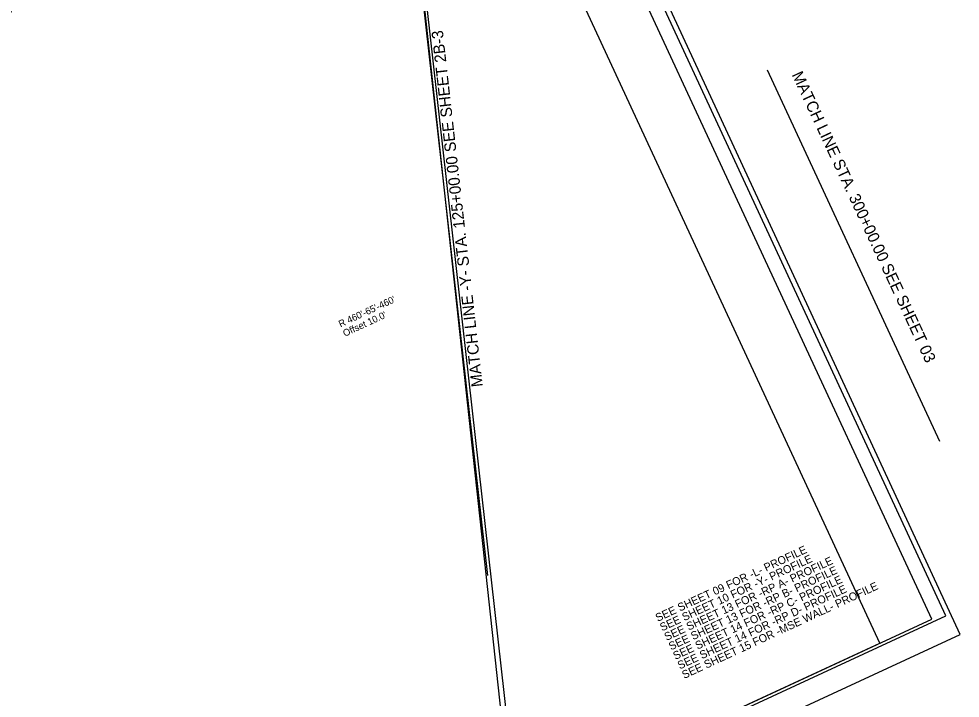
# Model space of a CAD drawing. Extents: x 1722892 to 1724880, y 971019 to 972720.
# Drawn here: x 1724057 to 1724880, y 971671 to 972266 of the extents above; entities that cross this region are included whole.
import ezdxf

# ---------------------------------------------------------------- set-up
doc = ezdxf.new("R2010")
doc.units = 0
for name, color, linetype in [('Matchline', 7, 'Continuous'), ('Matchline Text', 7, 'Continuous'), ('Prop Dimension', 7, 'Continuous'), ('Sheet Clip Boundary CELL', 7, 'Continuous'), ('Sheet Layout Plan Border', 7, 'Continuous'), ('Sheet Plan CELL', 7, 'Continuous'), ('Sheet Plot Border Inside CELL', 7, 'Continuous'), ('Sheet Plot Border Outside CELL', 7, 'Continuous')]:
    doc.layers.add(name, color=color, linetype=linetype)

msp = doc.modelspace()

# ---------------------------------------------------------------- linework, layer by layer
at = {"layer": 'Matchline'}
for p, q in [((1724467.08, 971778.29), (1724395.09, 972418.33)), ((1724711.39, 972221), (1724861.99, 971896.04))]:
    msp.add_line(p, q, dxfattribs=at)
at = {"layer": 'Sheet Clip Boundary CELL'}
msp.add_lwpolyline([(1723539.64, 971130.3), (1724809.87, 971718.99), (1724457.28, 972479.77), (1724285.57, 972400.19), (1724196.64, 972592.07), (1723098.13, 972082.96)], close=True, dxfattribs=at)
at = {"layer": 'Sheet Layout Plan Border'}
for points in [[(1724374.31, 972628.66), (1724393.21, 972460.35), (1724068.11, 972404.72), (1724049.69, 972271.07), (1723832.27, 972270.2), (1723815.72, 972244.69), (1723599.72, 972315.43), (1723098.13, 972082.96), (1723600.74, 971158.62), (1723483.33, 971374.55), (1723802.12, 971464.67), (1724031.92, 971474.7), (1724072.16, 971562.21), (1724326.28, 971494.87), (1724493, 971572.14)], [(1724391.63, 972460.07), (1724068.11, 972404.72), (1724049.69, 972271.07), (1723832.27, 972270.2), (1723815.72, 972244.69), (1723599.72, 972315.43), (1723098.13, 972082.96), (1723600.74, 971158.62), (1723483.33, 971374.55), (1723802.12, 971464.67), (1724031.92, 971474.7), (1724072.16, 971562.21), (1724326.28, 971494.87), (1724488.18, 971569.9)]]:
    msp.add_lwpolyline(points, close=True, dxfattribs=at)
at = {"layer": 'Sheet Plan CELL'}
msp.add_lwpolyline([(1724413.74, 972692.69), (1723052.76, 972061.94), (1723494.28, 971109.28), (1724855.24, 971740.02)], close=True, dxfattribs=at)
at = {"layer": 'Sheet Plot Border Inside CELL'}
msp.add_lwpolyline([(1723356.08, 971042.46), (1724867.62, 971743), (1724424.02, 972700.19), (1722912.46, 971999.66)], close=True, dxfattribs=at)
at = {"layer": 'Sheet Plot Border Outside CELL'}
msp.add_lwpolyline([(1723352.69, 971018.84), (1724880.13, 971726.74), (1724419.69, 972720.23), (1722892.25, 972012.33)], close=True, dxfattribs=at)

# ---------------------------------------------------------------- texts
at = {"layer": 'Matchline Text'}
for s, rotation, p in [('MATCH LINE -Y- STA. 125+00.00 SEE SHEET 2B-3', 96.4179, (1724462.66, 971943.86)), ('MATCH LINE STA. 300+00.00 SEE SHEET 03', 294.9147, (1724732.68, 972216.68))]:
    msp.add_text(s, height=10, rotation=rotation, dxfattribs=at).set_placement(p)
at = {"layer": 'Prop Dimension'}
for s, height, p in [("R 460'-65'-460' ", 6, (1724338.14, 971995.38)), ("Offset 10.0'", 6, (1724341.92, 971987.22)), ('SEE SHEET 09 FOR -L- PROFILE', 7, (1724615.55, 971737.69)), ('SEE SHEET 10 FOR -Y- PROFILE', 7, (1724619.41, 971729.37)), ('SEE SHEET 13 FOR -RP A- PROFILE', 7, (1724623.27, 971721.04)), ('SEE SHEET 13 FOR -RP B- PROFILE', 7, (1724627.13, 971712.72)), ('SEE SHEET 14 FOR -RP C- PROFILE', 7, (1724630.99, 971704.39)), ('SEE SHEET 14 FOR -RP D- PROFILE', 7, (1724634.85, 971696.07)), ('SEE SHEET 15 FOR -MSE WALL- PROFILE', 7, (1724638.71, 971687.74))]:
    msp.add_text(s, height=height, rotation=24.8656, dxfattribs=at).set_placement(p)

doc.saveas('drawing.dxf')
